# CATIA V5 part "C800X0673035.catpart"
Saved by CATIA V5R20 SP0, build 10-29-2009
Part number: C800X0673035
Source: Unknown
Property "A": "45"
Property "ARTICLENO": "C800X0673035"
Property "B": "22"
Property "BOMINFO": "C800X0673035"
Property "C": "65"
Property "CA": "C800X0673035"
Property "D1": "80"
Property "DES": "ROTATING EYEBOLT WITH RING Ton 6,7 M30x35"
Property "E": "71"
Property "H": "156"
Property "L": "35"
Property "LINA": "C800X0673035"
Property "NB": "C800X0673035"
Property "NBSYN": "$CODE."
Property "NN": "C800X"
Property "NT": "Rotating eyebolt with ring"
Property "SIZE": "M30"
Property "SUPPLIER": "CF"
Property "SW": "70"
Property "WEIGHT": "2850"
Property "WLL": "6.70"
Bounding box of the stored display mesh (mm): x -44.333 to 44.5, y -35 to 177.644, z -40 to 40
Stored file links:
  C:\Users\Utente\Desktop\3D files 800X\C800X0673035.catpart

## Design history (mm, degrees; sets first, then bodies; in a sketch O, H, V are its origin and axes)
Body1 "Geometry.1" (main body)
  Solid1 "C800X0673035.catpart": solid without history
